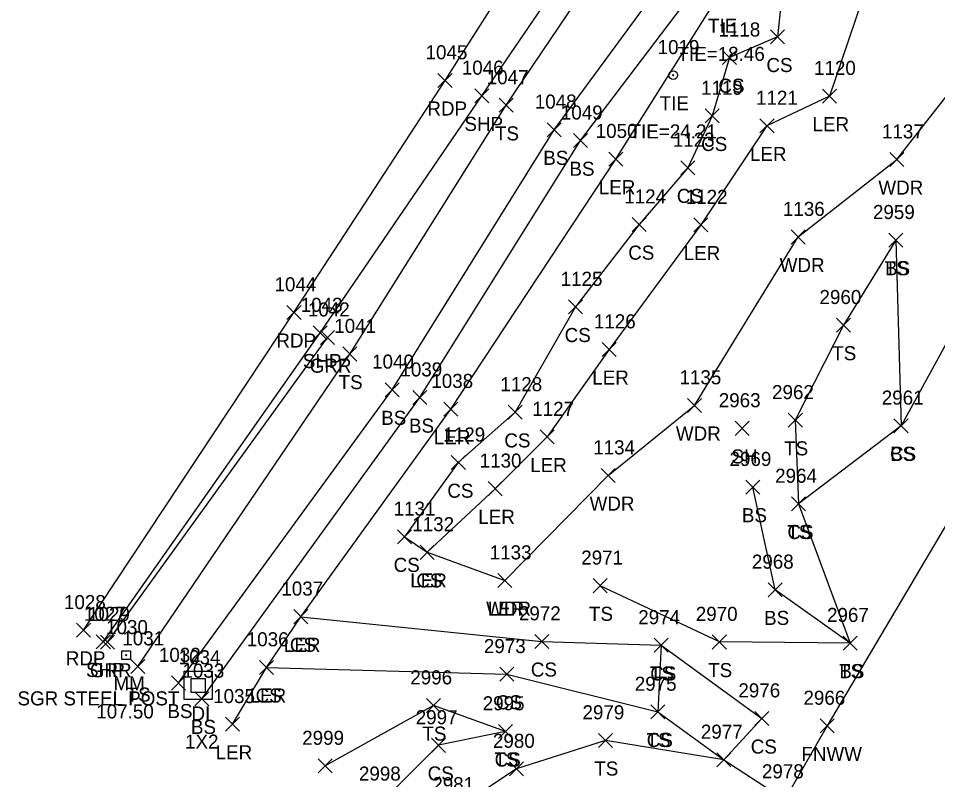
# Model space of a CAD drawing. Extents: x 1483143 to 1488182, y 802902 to 807581.
# Drawn here: x 1487039.3 to 1487170.1, y 804884.8 to 804993.1 of the extents above; entities that cross this region are included whole.
import ezdxf

# ---------------------------------------------------------------- set-up
doc = ezdxf.new("R2010")
doc.units = 0
for name, color, linetype in [('C_A', 7, 'Continuous'), ('C_C', 7, 'Continuous'), ('C_I', 7, 'Continuous'), ('CBP', 7, 'Continuous'), ('D_A', 7, 'Continuous'), ('D_C', 7, 'Continuous'), ('D_I', 7, 'Continuous'), ('DS', 7, 'Continuous'), ('L_A', 7, 'Continuous'), ('L_I', 7, 'Continuous'), ('L_TIC', 7, 'Continuous'), ('LARO', 7, 'Continuous'), ('LAWA', 7, 'Continuous'), ('LELB', 7, 'Continuous'), ('LFNC', 7, 'Continuous'), ('P_A', 7, 'Continuous'), ('P_I', 7, 'Continuous'), ('P_TIC', 7, 'Continuous'), ('PET', 7, 'Continuous'), ('PSP', 7, 'Continuous'), ('R_A', 7, 'Continuous'), ('R_C', 7, 'Continuous'), ('R_I', 7, 'Continuous'), ('R_TIC', 7, 'Continuous'), ('RGR', 7, 'Continuous'), ('S_A', 7, 'Continuous'), ('S_C', 7, 'Continuous'), ('S_I', 7, 'Continuous'), ('SRM', 7, 'Continuous')]:
    doc.layers.add(name, color=color, linetype=linetype)

msp = doc.modelspace()

# ---------------------------------------------------------------- linework, layer by layer
at = {"layer": 'CBP'}
for radius in [0.625, 0.0833]:
    msp.add_circle((1487132.48, 804985.06), radius, dxfattribs=at)
at = {"layer": 'DS'}
for p, q in [((1487062.88, 804900.25), (1487066.88, 804900.25)), ((1487062.88, 804896.25), (1487062.88, 804900.25)), ((1487066.88, 804900.25), (1487066.88, 804896.25)), ((1487063.88, 804897.25), (1487063.88, 804899.25)), ((1487063.88, 804899.25), (1487065.88, 804899.25)), ((1487064.88, 804898.25), (1487064.88, 804898.25)), ((1487064.88, 804898.25), (1487064.88, 804898.25)), ((1487065.88, 804899.25), (1487065.88, 804897.25)), ((1487065.88, 804897.25), (1487063.88, 804897.25)), ((1487066.88, 804896.25), (1487062.88, 804896.25))]:
    msp.add_line(p, q, dxfattribs=at)
at = {"layer": 'L_TIC'}
for points in [[(1487146.3, 804989.5), (1487148.3, 804991.5)], [(1487148.3, 804989.5), (1487146.3, 804991.5)], [(1487139.47, 804986.56), (1487141.47, 804988.56)], [(1487141.47, 804986.56), (1487139.47, 804988.56)], [(1487153.72, 804981.09), (1487155.72, 804983.09)], [(1487155.72, 804981.09), (1487153.72, 804983.09)], [(1487107.71, 804979.78), (1487109.71, 804981.78)], [(1487109.71, 804979.78), (1487107.71, 804981.78)], [(1487137.01, 804978.27), (1487139.01, 804980.27)], [(1487139.01, 804978.27), (1487137.01, 804980.27)], [(1487114.55, 804976.3), (1487116.55, 804978.3)], [(1487116.55, 804976.3), (1487114.55, 804978.3)], [(1487144.82, 804976.85), (1487146.82, 804978.85)], [(1487146.82, 804976.85), (1487144.82, 804978.85)], [(1487118.27, 804974.75), (1487120.27, 804976.75)], [(1487120.27, 804974.75), (1487118.27, 804976.75)], [(1487123.31, 804972.13), (1487125.31, 804974.13)], [(1487125.31, 804972.13), (1487123.31, 804974.13)], [(1487133.54, 804970.88), (1487135.54, 804972.88)], [(1487135.54, 804970.88), (1487133.54, 804972.88)], [(1487163.31, 804972.06), (1487165.31, 804974.06)], [(1487165.31, 804972.06), (1487163.31, 804974.06)], [(1487126.64, 804962.81), (1487128.64, 804964.81)], [(1487128.64, 804962.81), (1487126.64, 804964.81)], [(1487135.39, 804962.75), (1487137.39, 804964.75)], [(1487137.39, 804962.75), (1487135.39, 804964.75)], [(1487149.27, 804961.04), (1487151.27, 804963.04)], [(1487151.27, 804961.04), (1487149.27, 804963.04)], [(1487163.17, 804960.59), (1487165.17, 804962.59)], [(1487165.17, 804960.59), (1487163.17, 804962.59)], [(1487163.17, 804960.59), (1487165.17, 804962.59)], [(1487165.17, 804960.59), (1487163.17, 804962.59)], [(1487117.59, 804951.09), (1487119.59, 804953.09)], [(1487119.59, 804951.09), (1487117.59, 804953.09)], [(1487155.69, 804948.5), (1487157.69, 804950.5)], [(1487157.69, 804948.5), (1487155.69, 804950.5)], [(1487122.38, 804945.04), (1487124.38, 804947.04)], [(1487124.38, 804945.04), (1487122.38, 804947.04)], [(1487085.46, 804944.39), (1487087.46, 804946.39)], [(1487087.46, 804944.39), (1487085.46, 804946.39)], [(1487091.49, 804939.31), (1487093.49, 804941.31)], [(1487093.49, 804939.31), (1487091.49, 804941.31)], [(1487095.44, 804938.2), (1487097.44, 804940.2)], [(1487097.44, 804938.2), (1487095.44, 804940.2)], [(1487134.5, 804937.08), (1487136.5, 804939.08)], [(1487136.5, 804937.08), (1487134.5, 804939.08)], [(1487099.84, 804936.56), (1487101.84, 804938.56)], [(1487101.84, 804936.56), (1487099.84, 804938.56)], [(1487109, 804936.1), (1487111, 804938.1)], [(1487111, 804936.1), (1487109, 804938.1)], [(1487148.85, 804934.97), (1487150.85, 804936.97)], [(1487150.85, 804934.97), (1487148.85, 804936.97)], [(1487163.89, 804934.19), (1487165.89, 804936.19)], [(1487165.89, 804934.19), (1487163.89, 804936.19)], [(1487163.89, 804934.19), (1487165.89, 804936.19)], [(1487165.89, 804934.19), (1487163.89, 804936.19)], [(1487141.27, 804933.82), (1487143.27, 804935.82)], [(1487143.27, 804933.82), (1487141.27, 804935.82)], [(1487113.55, 804932.59), (1487115.55, 804934.59)], [(1487115.55, 804932.59), (1487113.55, 804934.59)], [(1487100.9, 804928.94), (1487102.9, 804930.94)], [(1487102.9, 804928.94), (1487100.9, 804930.94)], [(1487122.22, 804927.11), (1487124.22, 804929.11)], [(1487124.22, 804927.11), (1487122.22, 804929.11)], [(1487106.15, 804925.23), (1487108.15, 804927.23)], [(1487108.15, 804925.23), (1487106.15, 804927.23)], [(1487142.81, 804925.46), (1487144.81, 804927.46)], [(1487144.81, 804925.46), (1487142.81, 804927.46)], [(1487149.29, 804923.07), (1487151.29, 804925.07)], [(1487151.29, 804923.07), (1487149.29, 804925.07)], [(1487149.29, 804923.07), (1487151.29, 804925.07)], [(1487151.29, 804923.07), (1487149.29, 804925.07)], [(1487093.26, 804918.39), (1487095.26, 804920.39)], [(1487095.26, 804918.39), (1487093.26, 804920.39)], [(1487096.47, 804916.18), (1487098.47, 804918.18)], [(1487098.47, 804916.18), (1487096.47, 804918.18)], [(1487096.47, 804916.18), (1487098.47, 804918.18)], [(1487098.47, 804916.18), (1487096.47, 804918.18)], [(1487107.5, 804912.17), (1487109.5, 804914.17)], [(1487109.5, 804912.17), (1487107.5, 804914.17)], [(1487107.5, 804912.17), (1487109.5, 804914.17)], [(1487109.5, 804912.17), (1487107.5, 804914.17)], [(1487121.08, 804911.43), (1487123.08, 804913.43)], [(1487123.08, 804911.43), (1487121.08, 804913.43)], [(1487145.97, 804910.85), (1487147.97, 804912.85)], [(1487147.97, 804910.85), (1487145.97, 804912.85)], [(1487078.49, 804907.02), (1487080.49, 804909.02)], [(1487080.49, 804907.02), (1487078.49, 804909.02)], [(1487078.49, 804907.02), (1487080.49, 804909.02)], [(1487080.49, 804907.02), (1487078.49, 804909.02)], [(1487112.78, 804903.5), (1487114.78, 804905.5)], [(1487114.78, 804903.5), (1487112.78, 804905.5)], [(1487129.76, 804902.95), (1487131.76, 804904.95)], [(1487131.76, 804902.95), (1487129.76, 804904.95)], [(1487129.76, 804902.95), (1487131.76, 804904.95)], [(1487131.76, 804902.95), (1487129.76, 804904.95)], [(1487138.04, 804903.42), (1487140.04, 804905.42)], [(1487140.04, 804903.42), (1487138.04, 804905.42)], [(1487156.67, 804903.27), (1487158.67, 804905.27)], [(1487158.67, 804903.27), (1487156.67, 804905.27)], [(1487156.67, 804903.27), (1487158.67, 804905.27)], [(1487158.67, 804903.27), (1487156.67, 804905.27)], [(1487055.3, 804899.94), (1487057.3, 804901.94)], [(1487057.3, 804899.94), (1487055.3, 804901.94)], [(1487073.62, 804899.81), (1487075.62, 804901.81)], [(1487075.62, 804899.81), (1487073.62, 804901.81)], [(1487073.62, 804899.81), (1487075.62, 804901.81)], [(1487075.62, 804899.81), (1487073.62, 804901.81)], [(1487061.07, 804897.59), (1487063.07, 804899.59)], [(1487063.07, 804897.59), (1487061.07, 804899.59)], [(1487107.8, 804898.84), (1487109.8, 804900.84)], [(1487109.8, 804898.84), (1487107.8, 804900.84)], [(1487064.42, 804895.34), (1487066.42, 804897.34)], [(1487066.42, 804895.34), (1487064.42, 804897.34)], [(1487097.38, 804894.39), (1487099.38, 804896.39)], [(1487099.38, 804894.39), (1487097.38, 804896.39)], [(1487129.27, 804893.48), (1487131.27, 804895.48)], [(1487131.27, 804893.48), (1487129.27, 804895.48)], [(1487129.27, 804893.48), (1487131.27, 804895.48)], [(1487131.27, 804893.48), (1487129.27, 804895.48)], [(1487144.07, 804892.54), (1487146.07, 804894.54)], [(1487146.07, 804892.54), (1487144.07, 804894.54)], [(1487068.79, 804891.73), (1487070.79, 804893.73)], [(1487070.79, 804891.73), (1487068.79, 804893.73)], [(1487153.37, 804891.49), (1487155.37, 804893.49)], [(1487155.37, 804891.49), (1487153.37, 804893.49)], [(1487107.63, 804890.7), (1487109.63, 804892.7)], [(1487109.63, 804890.7), (1487107.63, 804892.7)], [(1487107.63, 804890.7), (1487109.63, 804892.7)], [(1487109.63, 804890.7), (1487107.63, 804892.7)], [(1487098.1, 804888.72), (1487100.1, 804890.72)], [(1487100.1, 804888.72), (1487098.1, 804890.72)], [(1487121.84, 804889.42), (1487123.84, 804891.42)], [(1487123.84, 804889.42), (1487121.84, 804891.42)], [(1487081.95, 804885.79), (1487083.95, 804887.79)], [(1487083.95, 804885.79), (1487081.95, 804887.79)], [(1487138.67, 804886.66), (1487140.67, 804888.66)], [(1487140.67, 804886.66), (1487138.67, 804888.66)], [(1487138.67, 804886.66), (1487140.67, 804888.66)], [(1487140.67, 804886.66), (1487138.67, 804888.66)], [(1487138.67, 804886.66), (1487140.67, 804888.66)], [(1487140.67, 804886.66), (1487138.67, 804888.66)], [(1487109.18, 804885.36), (1487111.18, 804887.36)], [(1487111.18, 804885.36), (1487109.18, 804887.36)]]:
    msp.add_lwpolyline(points, dxfattribs=at)
at = {"layer": 'LARO'}
for points in [[(1487224.88, 805102.18), (1487218.96, 805092.75), (1487207.16, 805077.22), (1487197.72, 805064.88), (1487191.27, 805052.19), (1487172.27, 805025.16), (1487162.87, 805006.15), (1487154.72, 804982.09), (1487145.82, 804977.85), (1487136.39, 804963.75), (1487123.38, 804946.04), (1487114.55, 804933.59), (1487107.15, 804926.23), (1487097.47, 804917.18), (1487108.5, 804913.17)], [(1487069.79, 804892.73), (1487074.62, 804900.81), (1487079.49, 804908.02), (1487100.84, 804937.56), (1487124.31, 804973.13), (1487145.49, 805006.81)]]:
    msp.add_lwpolyline(points, dxfattribs=at)
at = {"layer": 'LAWA'}
msp.add_lwpolyline([(1487108.5, 804913.17), (1487123.22, 804928.11), (1487135.5, 804938.08), (1487150.27, 804962.04), (1487164.31, 804973.06), (1487181.36, 804994.82)], dxfattribs=at)
at = {"layer": 'LELB'}
for points in [[(1487246.83, 805150.76), (1487242.89, 805139.86), (1487233.12, 805123.13), (1487224.88, 805102.18), (1487217.52, 805094.61), (1487202.79, 805080.03), (1487193.63, 805067.59), (1487187.1, 805055.56), (1487168.64, 805033.48), (1487158.81, 805020.55), (1487157.67, 805011.55), (1487148.3, 805000.05), (1487147.3, 804990.5), (1487140.47, 804987.56), (1487138.01, 804979.27), (1487134.54, 804971.88), (1487127.64, 804963.81), (1487118.59, 804952.09), (1487110, 804937.1), (1487101.9, 804929.94), (1487094.26, 804919.39), (1487097.47, 804917.18)], [(1487056.3, 804900.94), (1487086.46, 804945.39), (1487108.71, 804980.78), (1487132.66, 805016.32)], [(1487062.07, 804898.59), (1487092.49, 804940.31), (1487115.55, 804977.3), (1487141.45, 805012.57)], [(1487065.42, 804896.34), (1487096.44, 804939.2), (1487119.27, 804975.75), (1487145.32, 805010.11)], [(1487191.44, 804979.39), (1487179.24, 804961.36), (1487164.89, 804935.19), (1487150.29, 804924.07)], [(1487164.17, 804961.59), (1487156.69, 804949.5), (1487149.85, 804935.97), (1487150.29, 804924.07), (1487157.67, 804904.27), (1487139.04, 804904.42), (1487122.08, 804912.43)], [(1487164.17, 804961.59), (1487164.89, 804935.19)], [(1487157.67, 804904.27), (1487146.97, 804911.85), (1487143.81, 804926.46)], [(1487079.49, 804908.02), (1487113.78, 804904.5), (1487130.76, 804903.95), (1487145.07, 804893.54), (1487139.67, 804887.66)], [(1487130.76, 804903.95), (1487130.27, 804894.48)], [(1487074.62, 804900.81), (1487108.8, 804899.84), (1487130.27, 804894.48), (1487139.67, 804887.66), (1487148.36, 804882.02)], [(1487108.63, 804891.7), (1487098.38, 804895.39), (1487082.95, 804886.79)], [(1487108.63, 804891.7), (1487099.1, 804889.72), (1487091.02, 804881.7)], [(1487139.67, 804887.66), (1487122.84, 804890.42), (1487110.18, 804886.36), (1487100.89, 804880.19), (1487110.29, 804866.11), (1487108.11, 804844.42)]]:
    msp.add_lwpolyline(points, dxfattribs=at)
at = {"layer": 'LFNC'}
msp.add_lwpolyline([(1487217.26, 805000.45), (1487203.24, 804976.05), (1487199.24, 804969.27), (1487190.78, 804954.58), (1487180.82, 804937.14), (1487154.37, 804892.49), (1487148.36, 804882.02), (1487142.35, 804871.96), (1487133.16, 804857.5), (1487126.45, 804846.14), (1487121.75, 804838.45), (1487115.32, 804841.37), (1487108.11, 804844.42)], dxfattribs=at)
at = {"layer": 'P_TIC'}
for points in [[(1487099.01, 804983.32), (1487101.01, 804985.32)], [(1487101.01, 804983.32), (1487099.01, 804985.32)], [(1487104.23, 804981.13), (1487106.23, 804983.13)], [(1487106.23, 804981.13), (1487104.23, 804983.13)], [(1487077.52, 804950.31), (1487079.52, 804952.31)], [(1487079.52, 804950.31), (1487077.52, 804952.31)], [(1487081.25, 804947.39), (1487083.25, 804949.39)], [(1487083.25, 804947.39), (1487081.25, 804949.39)], [(1487047.56, 804905.1), (1487049.56, 804907.1)], [(1487049.56, 804905.1), (1487047.56, 804907.1)], [(1487050.39, 804903.44), (1487052.39, 804905.44)], [(1487052.39, 804903.44), (1487050.39, 804905.44)]]:
    msp.add_lwpolyline(points, dxfattribs=at)
at = {"layer": 'PET'}
msp.add_lwpolyline([(1487048.56, 804906.1), (1487078.52, 804951.31), (1487100.01, 804984.32), (1487124.37, 805022.55)], dxfattribs=at)
at = {"layer": 'PSP'}
msp.add_lwpolyline([(1487051.39, 804904.44), (1487082.25, 804948.39), (1487105.23, 804982.13), (1487129.96, 805018.35)], dxfattribs=at)
at = {"layer": 'R_TIC'}
for points in [[(1487082.27, 804946.73), (1487084.27, 804948.73)], [(1487084.27, 804946.73), (1487082.27, 804948.73)], [(1487051, 804903.4), (1487053, 804905.4)], [(1487053, 804903.4), (1487051, 804905.4)]]:
    msp.add_lwpolyline(points, dxfattribs=at)
at = {"layer": 'RGR'}
msp.add_lwpolyline([(1487052, 804904.4), (1487083.27, 804947.73)], dxfattribs=at)
at = {"layer": 'SRM'}
msp.add_lwpolyline([(1487054.01, 804903.16), (1487055.26, 804903.16), (1487055.26, 804901.91), (1487054.01, 804901.91)], close=True, dxfattribs=at)
msp.add_circle((1487054.64, 804902.54), 0.0833, dxfattribs=at)

# ---------------------------------------------------------------- texts
at = {"layer": 'C_A'}
for p in [(1487137.42, 804991.09), (1487130.55, 804980.06)]:
    msp.add_text('TIE', height=2, dxfattribs=at).set_placement(p)
at = {"layer": 'C_C'}
for s, p in [('TIE=18.46', (1487133.09, 804987.09)), ('TIE=24.21', (1487126.27, 804976.06))]:
    msp.add_text(s, height=2, dxfattribs=at).set_placement(p)
at = {"layer": 'C_I'}
msp.add_text('1019', height=2, dxfattribs=at).set_placement((1487130.26, 804988.06))
at = {"layer": 'D_A'}
msp.add_text('DI', height=2, dxfattribs=at).set_placement((1487063.94, 804893.25))
at = {"layer": 'D_C'}
msp.add_text('1X2', height=2, dxfattribs=at).set_placement((1487063.02, 804889.25))
at = {"layer": 'D_I'}
msp.add_text('1034', height=2, dxfattribs=at).set_placement((1487062.11, 804901.25))
at = {"layer": 'L_A'}
for s, p in [('CS', (1487145.74, 804985.5)), ('CS', (1487138.91, 804982.56)), ('LER', (1487152.3, 804977.09)), ('TS', (1487107.12, 804975.78)), ('CS', (1487136.45, 804974.27)), ('BS', (1487113.99, 804972.3)), ('LER', (1487143.4, 804972.85)), ('BS', (1487117.71, 804970.75)), ('LER', (1487121.89, 804968.13)), ('CS', (1487132.99, 804966.88)), ('WDR', (1487161.67, 804968.06)), ('CS', (1487126.08, 804958.81)), ('LER', (1487133.97, 804958.75)), ('WDR', (1487147.63, 804957.04)), ('TS', (1487162.57, 804956.59)), ('BS', (1487162.61, 804956.59)), ('CS', (1487117.03, 804947.09)), ('TS', (1487155.1, 804944.5)), ('LER', (1487120.96, 804941.04)), ('TS', (1487084.87, 804940.39)), ('BS', (1487090.93, 804935.31)), ('BS', (1487094.88, 804934.2)), ('WDR', (1487132.86, 804933.08)), ('LER', (1487098.42, 804932.56)), ('CS', (1487108.45, 804932.1)), ('TS', (1487148.26, 804930.97)), ('SH', (1487140.76, 804929.82)), ('CS', (1487163.33, 804930.19)), ('BS', (1487163.33, 804930.19)), ('LER', (1487112.13, 804928.59)), ('CS', (1487100.34, 804924.94)), ('WDR', (1487120.58, 804923.11)), ('LER', (1487104.74, 804921.23)), ('BS', (1487142.25, 804921.46)), ('TS', (1487148.7, 804919.07)), ('CS', (1487148.73, 804919.07)), ('CS', (1487092.7, 804914.39)), ('LER', (1487095.06, 804912.18)), ('CS', (1487095.92, 804912.18)), ('WDR', (1487105.86, 804908.17)), ('LER', (1487106.08, 804908.17)), ('TS', (1487120.49, 804907.43)), ('BS', (1487145.41, 804906.85)), ('LER', (1487077.08, 804903.02)), ('CS', (1487077.93, 804903.02)), ('CS', (1487112.22, 804899.5)), ('TS', (1487129.17, 804898.95)), ('CS', (1487129.21, 804898.95)), ('TS', (1487137.45, 804899.42)), ('TS', (1487156.08, 804899.27)), ('BS', (1487156.11, 804899.27)), ('TS', (1487054.71, 804895.94)), ('LER', (1487072.21, 804895.81)), ('CS', (1487073.06, 804895.81)), ('BS', (1487060.51, 804893.59)), ('CS', (1487107.24, 804894.84)), ('BS', (1487063.86, 804891.34)), ('TS', (1487096.79, 804890.39)), ('TS', (1487128.68, 804889.48)), ('CS', (1487128.71, 804889.48)), ('CS', (1487143.51, 804888.54)), ('LER', (1487067.37, 804887.73)), ('FNWW', (1487150.72, 804887.49)), ('TS', (1487107.04, 804886.7)), ('CS', (1487107.07, 804886.7)), ('CS', (1487097.54, 804884.72)), ('TS', (1487121.25, 804885.42))]:
    msp.add_text(s, height=2, dxfattribs=at).set_placement(p)
at = {"layer": 'L_I'}
for s, p in [('1118', (1487138.91, 804990.56)), ('1120', (1487152.51, 804985.09)), ('1047', (1487105.94, 804983.78)), ('1119', (1487136.44, 804982.27)), ('1048', (1487112.78, 804980.3)), ('1121', (1487144.26, 804980.85)), ('1049', (1487116.49, 804978.75)), ('1050', (1487121.45, 804976.13)), ('1137', (1487162.18, 804976.06)), ('1123', (1487132.42, 804974.88)), ('1124', (1487125.51, 804966.81)), ('1122', (1487134.26, 804966.75)), ('1136', (1487148.08, 804965.04)), ('2959', (1487160.9, 804964.59)), ('2959', (1487160.9, 804964.59)), ('1125', (1487116.46, 804955.09)), ('2960', (1487153.29, 804952.5)), ('1126', (1487121.19, 804949.04)), ('1041', (1487084.25, 804948.39)), ('1040', (1487089.63, 804943.31)), ('1039', (1487093.66, 804942.2)), ('1135', (1487133.37, 804941.08)), ('1038', (1487098.06, 804940.56)), ('1128', (1487107.88, 804940.1)), ('2962', (1487146.54, 804938.97)), ('2961', (1487162.15, 804938.19)), ('2961', (1487162.15, 804938.19)), ('2963', (1487138.96, 804937.82)), ('1127', (1487112.42, 804936.59)), ('1129', (1487099.77, 804932.94)), ('1134', (1487121.09, 804931.11)), ('1130', (1487104.94, 804929.23)), ('2969', (1487140.49, 804929.46)), ('2964', (1487146.98, 804927.07)), ('2964', (1487146.98, 804927.07)), ('1131', (1487092.7, 804922.39)), ('1132', (1487095.35, 804920.18)), ('1132', (1487095.35, 804920.18)), ('1133', (1487106.37, 804916.17)), ('1133', (1487106.37, 804916.17)), ('2971', (1487119.39, 804915.43)), ('2968', (1487143.67, 804914.85)), ('1037', (1487076.72, 804911.02)), ('1037', (1487076.72, 804911.02)), ('2972', (1487110.52, 804907.5)), ('2974', (1487127.5, 804906.95)), ('2974', (1487127.5, 804906.95)), ('2970', (1487135.69, 804907.42)), ('2967', (1487154.36, 804907.27)), ('2967', (1487154.36, 804907.27)), ('1031', (1487054.1, 804903.94)), ('1036', (1487071.8, 804903.81)), ('1036', (1487071.8, 804903.81)), ('2973', (1487105.54, 804902.84)), ('1032', (1487059.3, 804901.59)), ('1033', (1487062.65, 804899.34)), ('2996', (1487095.07, 804898.39)), ('2975', (1487127.01, 804897.48)), ('2975', (1487127.01, 804897.48)), ('2976', (1487141.75, 804896.54)), ('1035', (1487067.02, 804895.73)), ('2966', (1487151.01, 804895.49)), ('2995', (1487105.37, 804894.7)), ('2995', (1487105.37, 804894.7)), ('2997', (1487095.84, 804892.72)), ('2979', (1487119.57, 804893.42)), ('2999', (1487079.69, 804889.79)), ('2977', (1487136.41, 804890.66)), ('2977', (1487136.41, 804890.66)), ('2977', (1487136.41, 804890.66)), ('2980', (1487106.83, 804889.36)), ('2998', (1487087.76, 804884.7)), ('2978', (1487145.1, 804885.02)), ('2978', (1487145.1, 804885.02)), ('2981', (1487098.2, 804883.19))]:
    msp.add_text(s, height=2, dxfattribs=at).set_placement(p)
at = {"layer": 'P_A'}
for s, p in [('RDP', (1487097.5, 804979.32)), ('SHP', (1487102.77, 804977.13)), ('RDP', (1487076.01, 804946.31)), ('SHP', (1487079.78, 804943.39)), ('RDP', (1487046.05, 804901.1)), ('SHP', (1487048.93, 804899.44))]:
    msp.add_text(s, height=2, dxfattribs=at).set_placement(p)
at = {"layer": 'P_I'}
for s, p in [('1045', (1487097.24, 804987.32)), ('1046', (1487102.4, 804985.13)), ('1044', (1487075.75, 804954.31)), ('1043', (1487079.48, 804951.39)), ('1028', (1487045.79, 804909.1)), ('1027', (1487048.62, 804907.44))]:
    msp.add_text(s, height=2, dxfattribs=at).set_placement(p)
at = {"layer": 'R_A'}
for p in [(1487080.76, 804942.73), (1487049.48, 804899.4)]:
    msp.add_text('GRR', height=2, dxfattribs=at).set_placement(p)
at = {"layer": 'R_C'}
msp.add_text('SGR STEEL POST', height=2, dxfattribs=at).set_placement((1487039.18, 804895.4))
at = {"layer": 'R_I'}
for s, p in [('1042', (1487080.5, 804950.73)), ('1029', (1487049.22, 804907.4))]:
    msp.add_text(s, height=2, dxfattribs=at).set_placement(p)
at = {"layer": 'S_A'}
msp.add_text('MM', height=2, dxfattribs=at).set_placement((1487052.83, 804897.54))
at = {"layer": 'S_C'}
msp.add_text('107.50', height=2, dxfattribs=at).set_placement((1487050.39, 804893.54))
at = {"layer": 'S_I'}
msp.add_text('1030', height=2, dxfattribs=at).set_placement((1487051.78, 804905.54))

doc.saveas('drawing.dxf')
